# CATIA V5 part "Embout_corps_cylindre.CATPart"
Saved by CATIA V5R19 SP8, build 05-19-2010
Part number: Embout_corps_cylindre
Revision: ANY
Definition: UNKNOWN
Nomenclature: 3
Source: Unknown
Bounding box of the stored display mesh (mm): x -13.5 to 0, y -18 to 18, z -12 to 10
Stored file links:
  D:\Documents\1_Travail\2- 2I2D\1 - Cours et TD\2- TD\3-TD Assemblage\Pompe AirMan\Embout_corps_cylindre.CATPart
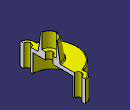
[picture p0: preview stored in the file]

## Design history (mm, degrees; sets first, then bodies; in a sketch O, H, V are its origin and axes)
Body1 "Congé3" (main body)
  Solid1: solid without history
